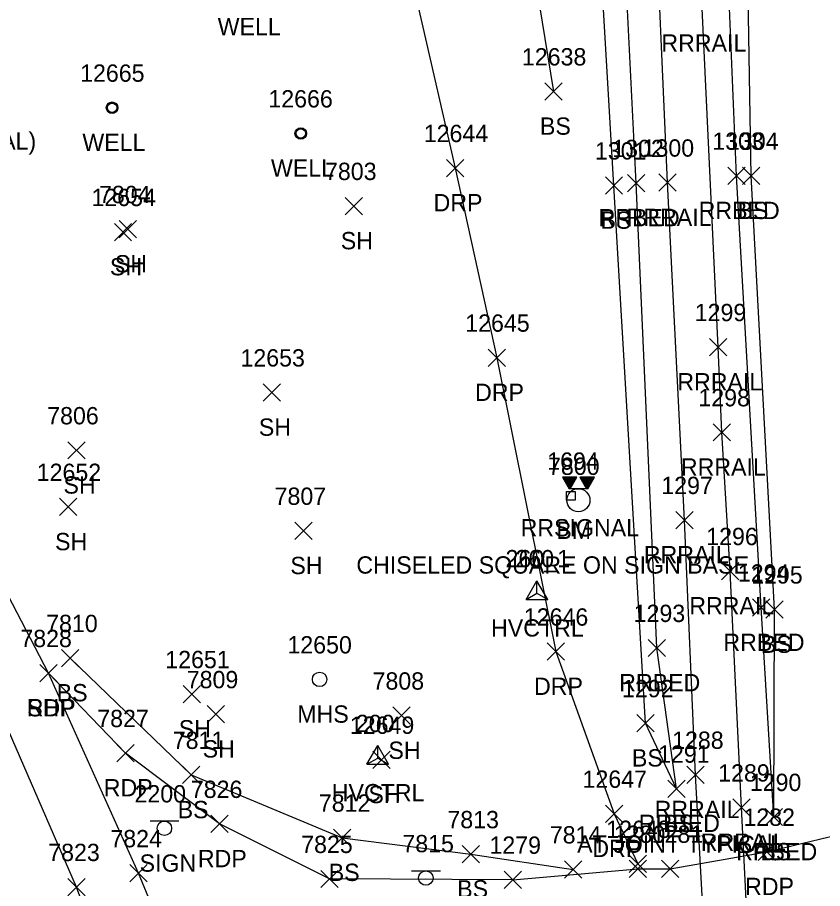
# Model space of a CAD drawing. Extents: x 1769141 to 1770817, y 735471 to 742405.
# Drawn here: x 1770083.4 to 1770176.3, y 741110.6 to 741211.2 of the extents above; entities that cross this region are included whole.
import ezdxf

# ---------------------------------------------------------------- set-up
doc = ezdxf.new("R2010")
doc.units = 0
for name, color, linetype in [('C_A', 7, 'Continuous'), ('C_C', 7, 'Continuous'), ('C_I', 7, 'Continuous'), ('CPBM', 7, 'Continuous'), ('CPSM', 7, 'Continuous'), ('L_A', 7, 'Continuous'), ('L_I', 7, 'Continuous'), ('L_TIC', 7, 'Continuous'), ('LELB', 7, 'Continuous'), ('P_A', 7, 'Continuous'), ('P_I', 7, 'Continuous'), ('P_TIC', 7, 'Continuous'), ('PET', 7, 'Continuous'), ('PSP', 7, 'Continuous'), ('R_A', 7, 'Continuous'), ('R_C', 7, 'Continuous'), ('R_I', 7, 'Continuous'), ('R_TIC', 7, 'Continuous'), ('RDP', 7, 'Continuous'), ('RR', 7, 'Continuous'), ('RRB', 7, 'Continuous'), ('S_A', 7, 'Continuous'), ('S_I', 7, 'Continuous'), ('SSGN', 7, 'Continuous'), ('TCSH', 7, 'Continuous'), ('U_A', 7, 'Continuous'), ('U_C', 7, 'Continuous'), ('U_I', 7, 'Continuous'), ('USMH', 7, 'Continuous'), ('UWW', 7, 'Continuous')]:
    doc.layers.add(name, color=color, linetype=linetype)

msp = doc.modelspace()

# ---------------------------------------------------------------- linework, layer by layer
at = {"layer": 'CPBM'}
for p, q in [((1770146.79, 741155.5), (1770146.79, 741156.5)), ((1770146.79, 741156.5), (1770147.79, 741156.5)), ((1770147.29, 741156), (1770147.29, 741156)), ((1770147.29, 741156), (1770147.29, 741156)), ((1770147.79, 741156.5), (1770147.79, 741155.5)), ((1770147.79, 741155.5), (1770146.79, 741155.5))]:
    msp.add_line(p, q, dxfattribs=at)
at = {"layer": 'CPSM'}
for p, q in [((1770142.12, 741144.01), (1770143.37, 741146.18)), ((1770142.12, 741144.01), (1770143.37, 741146.18)), ((1770144.62, 741144.01), (1770143.37, 741146.18)), ((1770143.37, 741144.74), (1770143.37, 741146.18)), ((1770144.62, 741144.01), (1770143.37, 741146.18)), ((1770143.37, 741144.74), (1770143.37, 741146.18)), ((1770142.12, 741144.01), (1770143.37, 741144.74)), ((1770142.12, 741144.01), (1770143.37, 741144.74)), ((1770143.37, 741144.74), (1770143.37, 741144.74)), ((1770143.37, 741144.74), (1770144.62, 741144.01)), ((1770143.37, 741144.74), (1770143.37, 741144.74)), ((1770143.37, 741144.74), (1770144.62, 741144.01)), ((1770142.12, 741144.01), (1770144.62, 741144.01)), ((1770142.12, 741144.01), (1770144.62, 741144.01)), ((1770123.73, 741124.98), (1770124.98, 741127.14)), ((1770126.23, 741124.98), (1770124.98, 741127.14)), ((1770124.99, 741125.7), (1770124.98, 741127.14)), ((1770123.73, 741124.98), (1770124.99, 741125.7)), ((1770124.99, 741125.7), (1770124.99, 741125.7)), ((1770124.99, 741125.7), (1770126.23, 741124.98)), ((1770123.73, 741124.98), (1770126.23, 741124.98))]:
    msp.add_line(p, q, dxfattribs=at)
at = {"layer": 'L_TIC'}
for points in [[(1770144.27, 741201.69), (1770146.27, 741203.69)], [(1770146.27, 741201.69), (1770144.27, 741203.69)], [(1770167.08, 741191.95), (1770169.08, 741193.95)], [(1770169.08, 741191.95), (1770167.08, 741193.95)], [(1770151.26, 741190.83), (1770153.26, 741192.83)], [(1770153.26, 741190.83), (1770151.26, 741192.83)], [(1770121.24, 741188.46), (1770123.24, 741190.46)], [(1770123.24, 741188.46), (1770121.24, 741190.46)], [(1770094.58, 741185.45), (1770096.58, 741187.45)], [(1770096.58, 741185.45), (1770094.58, 741187.45)], [(1770095.15, 741185.79), (1770097.15, 741187.79)], [(1770097.15, 741185.79), (1770095.15, 741187.79)], [(1770111.78, 741166.92), (1770113.78, 741168.92)], [(1770113.78, 741166.92), (1770111.78, 741168.92)], [(1770089.22, 741160.24), (1770091.22, 741162.24)], [(1770091.22, 741160.24), (1770089.22, 741162.24)], [(1770088.26, 741153.7), (1770090.26, 741155.7)], [(1770090.26, 741153.7), (1770088.26, 741155.7)], [(1770115.42, 741150.94), (1770117.42, 741152.94)], [(1770117.42, 741150.94), (1770115.42, 741152.94)], [(1770169.78, 741141.85), (1770171.78, 741143.85)], [(1770171.78, 741141.85), (1770169.78, 741143.85)], [(1770088.49, 741136.25), (1770090.49, 741138.25)], [(1770090.49, 741136.25), (1770088.49, 741138.25)], [(1770102.53, 741132.08), (1770104.53, 741134.08)], [(1770104.53, 741132.08), (1770102.53, 741134.08)], [(1770105.29, 741129.76), (1770107.29, 741131.76)], [(1770107.29, 741129.76), (1770105.29, 741131.76)], [(1770126.73, 741129.6), (1770128.73, 741131.6)], [(1770128.73, 741129.6), (1770126.73, 741131.6)], [(1770154.88, 741128.72), (1770156.88, 741130.72)], [(1770156.88, 741128.72), (1770154.88, 741130.72)], [(1770124.42, 741124.49), (1770126.42, 741126.49)], [(1770126.42, 741124.49), (1770124.42, 741126.49)], [(1770102.45, 741122.75), (1770104.45, 741124.75)], [(1770104.45, 741122.75), (1770102.45, 741124.75)], [(1770158.47, 741121.16), (1770160.47, 741123.16)], [(1770160.47, 741121.16), (1770158.47, 741123.16)], [(1770169.72, 741117.89), (1770171.72, 741119.89)], [(1770171.72, 741117.89), (1770169.72, 741119.89)], [(1770119.89, 741115.5), (1770121.89, 741117.5)], [(1770121.89, 741115.5), (1770119.89, 741117.5)], [(1770134.72, 741113.59), (1770136.72, 741115.59)], [(1770136.72, 741113.59), (1770134.72, 741115.59)], [(1770146.55, 741111.83), (1770148.55, 741113.83)], [(1770148.55, 741111.83), (1770146.55, 741113.83)]]:
    msp.add_lwpolyline(points, dxfattribs=at)
at = {"layer": 'LELB'}
for points in [[(1770159.47, 741122.16), (1770155.88, 741129.72), (1770152.26, 741191.83), (1770148.79, 741250.94), (1770147.9, 741304.26), (1770146.46, 741364.5), (1770147.88, 741419.38), (1770149.7, 741479.08), (1770152.69, 741545.1), (1770155.76, 741599.64), (1770158.96, 741639.34), (1770162.27, 741670.36), (1770169.16, 741728.31), (1770174.08, 741769.97), (1770179.32, 741804.69), (1770187.63, 741847.88), (1770194.61, 741886.57)], [(1770170.72, 741118.89), (1770170.78, 741142.85), (1770168.08, 741192.95), (1770167.14, 741250.65), (1770163.56, 741305.09), (1770162.91, 741364.69), (1770162.95, 741418.42), (1770164.45, 741477.75), (1770168.47, 741544.61), (1770171.96, 741598.42), (1770177.16, 741637.54), (1770178.36, 741670.05), (1770184.18, 741725.16), (1770189.43, 741766.84), (1770194.19, 741801.42), (1770201.5, 741845.17), (1770207.42, 741883.86)], [(1770138.33, 741423.16), (1770133.9, 741361.32), (1770128.63, 741312.35), (1770126.33, 741301.84), (1770135.84, 741298.8), (1770136.67, 741255.46), (1770145.27, 741202.69)], [(1770089.49, 741137.25), (1770103.45, 741123.75), (1770120.89, 741116.5), (1770135.72, 741114.59), (1770147.55, 741112.83)]]:
    msp.add_lwpolyline(points, dxfattribs=at)
at = {"layer": 'P_TIC'}
for points in [[(1770085.99, 741134.51), (1770087.99, 741136.51)], [(1770087.99, 741134.51), (1770085.99, 741136.51)], [(1770085.99, 741134.51), (1770087.99, 741136.51)], [(1770087.99, 741134.51), (1770085.99, 741136.51)], [(1770094.87, 741125.27), (1770096.87, 741127.27)], [(1770096.87, 741125.27), (1770094.87, 741127.27)], [(1770105.73, 741117.09), (1770107.73, 741119.09)], [(1770107.73, 741117.09), (1770105.73, 741119.09)], [(1770168.9, 741113.87), (1770170.9, 741115.87)], [(1770170.9, 741113.87), (1770168.9, 741115.87)], [(1770154.01, 741111.9), (1770156.01, 741113.9)], [(1770156.01, 741111.9), (1770154.01, 741113.9)], [(1770157.73, 741111.91), (1770159.73, 741113.91)], [(1770159.73, 741111.91), (1770157.73, 741113.91)], [(1770096.38, 741111.39), (1770098.38, 741113.39)], [(1770098.38, 741111.39), (1770096.38, 741113.39)], [(1770118.41, 741110.73), (1770120.41, 741112.73)], [(1770120.41, 741110.73), (1770118.41, 741112.73)], [(1770139.58, 741110.64), (1770141.58, 741112.64)], [(1770141.58, 741110.64), (1770139.58, 741112.64)], [(1770089.21, 741109.8), (1770091.21, 741111.8)], [(1770091.21, 741109.8), (1770089.21, 741111.8)]]:
    msp.add_lwpolyline(points, dxfattribs=at)
at = {"layer": 'PET'}
for points in [[(1770133.59, 741007.28), (1770116.34, 741046.84), (1770099.4, 741086.12), (1770090.21, 741110.8), (1770080.18, 741133.86), (1770069.42, 741160.68), (1770059.06, 741185.91)], [(1770119.41, 741111.73), (1770106.73, 741118.09), (1770095.87, 741126.27), (1770086.99, 741135.51)], [(1770140.58, 741111.64), (1770155.01, 741112.9), (1770158.73, 741112.91), (1770169.9, 741114.87), (1770181.1, 741117.58), (1770187.57, 741118.74), (1770200.24, 741121.92), (1770219.15, 741127.59)], [(1770140.58, 741111.64), (1770119.41, 741111.73)]]:
    msp.add_lwpolyline(points, dxfattribs=at)
at = {"layer": 'PSP'}
msp.add_lwpolyline([(1770137.13, 741008.17), (1770123.03, 741049.87), (1770106.81, 741089.63), (1770097.38, 741112.39), (1770086.99, 741135.51), (1770073.46, 741161.45), (1770063.93, 741186.81)], dxfattribs=at)
at = {"layer": 'R_TIC'}
for points in [[(1770132.94, 741192.84), (1770134.94, 741194.84)], [(1770134.94, 741192.84), (1770132.94, 741194.84)], [(1770153.83, 741191.11), (1770155.83, 741193.11)], [(1770155.83, 741191.11), (1770153.83, 741193.11)], [(1770157.42, 741191.16), (1770159.42, 741193.16)], [(1770159.42, 741191.16), (1770157.42, 741193.16)], [(1770165.39, 741191.95), (1770167.39, 741193.95)], [(1770167.39, 741191.95), (1770165.39, 741193.95)], [(1770163.28, 741172.16), (1770165.28, 741174.16)], [(1770165.28, 741172.16), (1770163.28, 741174.16)], [(1770137.73, 741170.94), (1770139.73, 741172.94)], [(1770139.73, 741170.94), (1770137.73, 741172.94)], [(1770163.69, 741162.32), (1770165.69, 741164.32)], [(1770165.69, 741162.32), (1770163.69, 741164.32)], [(1770159.41, 741152.19), (1770161.41, 741154.19)], [(1770161.41, 741152.19), (1770159.41, 741154.19)], [(1770164.66, 741146.29), (1770166.66, 741148.29)], [(1770166.66, 741146.29), (1770164.66, 741148.29)], [(1770168.25, 741142.07), (1770170.25, 741144.07)], [(1770170.25, 741142.07), (1770168.25, 741144.07)], [(1770144.54, 741136.99), (1770146.54, 741138.99)], [(1770146.54, 741136.99), (1770144.54, 741138.99)], [(1770156.22, 741137.41), (1770158.22, 741139.41)], [(1770158.22, 741137.41), (1770156.22, 741139.41)], [(1770160.66, 741122.76), (1770162.66, 741124.76)], [(1770162.66, 741122.76), (1770160.66, 741124.76)], [(1770158.47, 741121.16), (1770160.47, 741123.16)], [(1770160.47, 741121.16), (1770158.47, 741123.16)], [(1770165.99, 741118.98), (1770167.99, 741120.98)], [(1770167.99, 741118.98), (1770165.99, 741120.98)], [(1770151.27, 741118.26), (1770153.27, 741120.26)], [(1770153.27, 741118.26), (1770151.27, 741120.26)], [(1770169.72, 741117.89), (1770171.72, 741119.89)], [(1770171.72, 741117.89), (1770169.72, 741119.89)], [(1770154, 741112.47), (1770156, 741114.47)], [(1770156, 741112.47), (1770154, 741114.47)]]:
    msp.add_lwpolyline(points, dxfattribs=at)
at = {"layer": 'RDP'}
msp.add_lwpolyline([(1770119.07, 741298.17), (1770129.43, 741296.15), (1770123.39, 741257.98), (1770122.93, 741246.96), (1770125.26, 741231.62), (1770133.94, 741193.84), (1770138.73, 741171.94), (1770145.54, 741137.99), (1770152.27, 741119.26), (1770155, 741113.47)], dxfattribs=at)
at = {"layer": 'RR'}
for points in [[(1770197.75, 740390.49), (1770195.85, 740429.49), (1770193.92, 740468.48), (1770191.99, 740507.45), (1770190.02, 740546.42), (1770188.18, 740585.45), (1770186.34, 740624.52), (1770184.35, 740663.53), (1770182.41, 740702.58), (1770181.02, 740730.45), (1770179.25, 740766.27), (1770177.16, 740810.3), (1770173.74, 740877.11), (1770171.32, 740927.71), (1770169.45, 740967.98), (1770167.61, 741006.36), (1770166.54, 741027.4), (1770165.65, 741046.21), (1770163.84, 741084.65), (1770161.66, 741123.76), (1770160.41, 741153.19), (1770158.42, 741192.16), (1770156.87, 741228.02)], [(1770203.66, 740370.75), (1770201.77, 740409.67), (1770199.78, 740448.72), (1770197.9, 740487.78), (1770195.96, 740526.73), (1770194.09, 740565.77), (1770192.14, 740604.84), (1770190.28, 740643.85), (1770188.29, 740682.87), (1770186.41, 740721.83), (1770184.15, 740770), (1770182.62, 740801.29), (1770179.63, 740862.12), (1770176.86, 740918.91), (1770174.1, 740971.71), (1770172.22, 741013.51), (1770171.36, 741030.47), (1770170.33, 741051.22), (1770168.96, 741081.09), (1770166.99, 741119.98), (1770165.66, 741147.29), (1770164.69, 741163.32), (1770164.28, 741173.16), (1770162.44, 741212.29)]]:
    msp.add_lwpolyline(points, dxfattribs=at)
at = {"layer": 'RRB'}
for points in [[(1770159.47, 741122.16), (1770157.22, 741138.41), (1770154.83, 741192.11), (1770151.88, 741250.64), (1770151.59, 741304.35), (1770150.34, 741364.24), (1770150.63, 741419.36), (1770151.12, 741479.07), (1770155.02, 741545.1), (1770158.66, 741599.97), (1770162.08, 741639.22), (1770165.85, 741670.35), (1770171.87, 741726.99), (1770176.74, 741769), (1770181.57, 741804.32), (1770188.88, 741847.51), (1770194.61, 741886.57), (1770198.24, 741898.62)], [(1770170.72, 741118.89), (1770169.25, 741143.07), (1770166.39, 741192.95), (1770164.02, 741250.29), (1770162.37, 741304.75), (1770161.63, 741364.62), (1770161.73, 741418.13), (1770163.48, 741477.78), (1770166.12, 741544.52), (1770169.96, 741598.79), (1770173.92, 741637.73), (1770176.8, 741669.78), (1770182.94, 741725.6), (1770188.11, 741766.81), (1770193.15, 741801.76), (1770199.69, 741845.61), (1770207.42, 741883.86)]]:
    msp.add_lwpolyline(points, dxfattribs=at)
at = {"layer": 'SSGN'}
for p, q in [((1770098.71, 741118.43), (1770102.04, 741118.43)), ((1770100.36, 741117.59), (1770100.36, 741117.59)), ((1770128.9, 741112.68), (1770132.23, 741112.68)), ((1770130.54, 741111.84), (1770130.54, 741111.84))]:
    msp.add_line(p, q, dxfattribs=at)
for centre in [(1770100.36, 741117.59), (1770130.54, 741111.84)]:
    msp.add_circle(centre, 0.833, dxfattribs=at)
at = {"layer": 'TCSH'}
for p, q in [((1770147.96, 741158.14), (1770146.3, 741158.14)), ((1770146.3, 741158.14), (1770147.07, 741156.81)), ((1770147.2, 741156.81), (1770147.96, 741158.14)), ((1770150, 741158.14), (1770148.33, 741158.14)), ((1770148.33, 741158.14), (1770149.1, 741156.81)), ((1770149.23, 741156.81), (1770150, 741158.14)), ((1770149.23, 741156.81), (1770147.07, 741156.81)), ((1770148.15, 741155.48), (1770148.15, 741155.48))]:
    msp.add_line(p, q, dxfattribs=at)
for points in [[(1770146.34, 741158.07), (1770147.92, 741158.07)], [(1770146.42, 741157.93), (1770147.84, 741157.93)], [(1770146.5, 741157.8), (1770147.77, 741157.8)], [(1770148.36, 741158.1), (1770149.97, 741158.1)], [(1770148.44, 741157.96), (1770149.89, 741157.96)], [(1770148.51, 741157.83), (1770149.82, 741157.83)], [(1770146.57, 741157.67), (1770147.69, 741157.67)], [(1770146.65, 741157.53), (1770147.61, 741157.53)], [(1770146.73, 741157.4), (1770147.54, 741157.4)], [(1770146.8, 741157.27), (1770147.46, 741157.27)], [(1770146.88, 741157.13), (1770147.38, 741157.13)], [(1770146.96, 741157), (1770147.3, 741157)], [(1770147.04, 741156.87), (1770147.23, 741156.87)], [(1770148.59, 741157.7), (1770149.74, 741157.7)], [(1770148.67, 741157.56), (1770149.66, 741157.56)], [(1770148.75, 741157.43), (1770149.59, 741157.43)], [(1770148.82, 741157.3), (1770149.51, 741157.3)], [(1770148.9, 741157.16), (1770149.43, 741157.16)], [(1770148.98, 741157.03), (1770149.36, 741157.03)], [(1770149.05, 741156.9), (1770149.28, 741156.9)]]:
    msp.add_lwpolyline(points, dxfattribs=at)
msp.add_circle((1770148.15, 741155.48), 1.33, dxfattribs=at)
at = {"layer": 'USMH'}
for p, q in [((1770118.28, 741134.78), (1770118.28, 741134.78)), ((1770119.12, 741134.78), (1770119.12, 741134.78))]:
    msp.add_line(p, q, dxfattribs=at)
msp.add_circle((1770118.28, 741134.78), 0.833, dxfattribs=at)
at = {"layer": 'UWW'}
for centre, radius in [((1770094.32, 741200.81), 0.667), ((1770094.32, 741200.81), 0.625), ((1770094.32, 741200.81), 0.583), ((1770094.32, 741200.81), 0.542), ((1770116.1, 741197.84), 0.667), ((1770116.1, 741197.84), 0.625), ((1770116.1, 741197.84), 0.583), ((1770116.1, 741197.84), 0.542)]:
    msp.add_circle(centre, radius, dxfattribs=at)

# ---------------------------------------------------------------- texts
at = {"layer": 'C_A'}
for s, p in [('BM', (1770145.6, 741151)), ('HVCTRL', (1770138.07, 741139.73)), ('HVCTRL', (1770138.07, 741139.73)), ('HVCTRL', (1770119.68, 741120.7))]:
    msp.add_text(s, height=2, dxfattribs=at).set_placement(p)
at = {"layer": 'C_C'}
msp.add_text('CHISELED SQUARE ON SIGN BASE', height=2, dxfattribs=at).set_placement((1770122.52, 741147))
at = {"layer": 'C_I'}
for s, p in [('1694', (1770144.55, 741159)), ('260_1', (1770139.74, 741147.73)), ('260', (1770140.88, 741147.73)), ('200', (1770122.46, 741128.7))]:
    msp.add_text(s, height=2, dxfattribs=at).set_placement(p)
at = {"layer": 'L_A'}
for s, p in [('BS', (1770143.71, 741197.69)), ('BS', (1770166.52, 741187.95)), ('BS', (1770150.7, 741186.83)), ('SH', (1770120.72, 741184.46)), ('SH', (1770094.07, 741181.45)), ('SH', (1770094.64, 741181.79)), ('SH', (1770111.26, 741162.92)), ('SH', (1770088.71, 741156.24)), ('SH', (1770087.74, 741149.7)), ('SH', (1770114.9, 741146.94)), ('BS', (1770169.22, 741137.85)), ('BS', (1770087.93, 741132.25)), ('SH', (1770102.02, 741128.08)), ('SH', (1770104.78, 741125.76)), ('SH', (1770126.22, 741125.6)), ('BS', (1770154.33, 741124.72)), ('SH', (1770123.91, 741120.49)), ('BS', (1770101.89, 741118.75)), ('BS', (1770157.92, 741117.16)), ('BS', (1770169.16, 741113.89)), ('BS', (1770119.33, 741111.5)), ('BS', (1770134.16, 741109.59))]:
    msp.add_text(s, height=2, dxfattribs=at).set_placement(p)
at = {"layer": 'L_I'}
for s, p in [('12638', (1770141.63, 741205.69)), ('1304', (1770165.31, 741195.95)), ('1301', (1770150.06, 741194.83)), ('7803', (1770118.9, 741192.46)), ('12654', (1770091.94, 741189.45)), ('7804', (1770092.81, 741189.79)), ('12653', (1770109.14, 741170.92)), ('7806', (1770086.83, 741164.24)), ('12652', (1770085.62, 741157.7)), ('7807', (1770113.08, 741154.94)), ('1295', (1770168.09, 741145.85)), ('7810', (1770086.71, 741140.25)), ('12651', (1770100.46, 741136.08)), ('7809', (1770102.94, 741133.76)), ('7808', (1770124.39, 741133.6)), ('1292', (1770153.19, 741132.72)), ('12649', (1770121.77, 741128.49)), ('7811', (1770101.33, 741126.75)), ('1291', (1770157.35, 741125.16)), ('1290', (1770167.94, 741121.89)), ('7812', (1770118.19, 741119.5)), ('7813', (1770133.03, 741117.59)), ('7814', (1770144.85, 741115.83))]:
    msp.add_text(s, height=2, dxfattribs=at).set_placement(p)
at = {"layer": 'P_A'}
for s, p in [('SHP', (1770084.52, 741130.51)), ('RDP', (1770084.47, 741130.51)), ('RDP', (1770093.36, 741121.27)), ('RDP', (1770104.22, 741113.09)), ('RDP', (1770167.39, 741109.87))]:
    msp.add_text(s, height=2, dxfattribs=at).set_placement(p)
at = {"layer": 'P_I'}
for s, p in [('7828', (1770083.73, 741138.51)), ('7828', (1770083.73, 741138.51)), ('7827', (1770092.61, 741129.27)), ('7826', (1770103.41, 741121.09)), ('1282', (1770167.2, 741117.87)), ('1280', (1770152.23, 741115.9)), ('1281', (1770156.61, 741115.91)), ('7824', (1770094.12, 741115.39)), ('7825', (1770116.15, 741114.73)), ('1279', (1770137.88, 741114.64)), ('7823', (1770086.95, 741113.8))]:
    msp.add_text(s, height=2, dxfattribs=at).set_placement(p)
at = {"layer": 'R_A'}
for s, p in [('RRRAIL', (1770157.73, 741207.29)), ('DRP', (1770131.43, 741188.84)), ('RRBED', (1770150.48, 741187.11)), ('RRRAIL', (1770153.71, 741187.16)), ('RRBED', (1770162.03, 741187.95)), ('RRRAIL', (1770159.57, 741168.16)), ('DRP', (1770136.22, 741166.94)), ('RRRAIL', (1770159.98, 741158.32)), ('RRSIGNAL', (1770141.48, 741151.3)), ('RRRAIL', (1770155.7, 741148.19)), ('RRRAIL', (1770160.95, 741142.29)), ('RRBED', (1770164.89, 741138.07)), ('DRP', (1770143.03, 741132.99)), ('RRBED', (1770152.86, 741133.41)), ('RRRAIL', (1770156.95, 741118.76)), ('RRBED', (1770155.12, 741117.16)), ('RRRAIL', (1770162.28, 741114.98)), ('DRP', (1770149.76, 741114.26)), ('RRBED', (1770166.36, 741113.89))]:
    msp.add_text(s, height=2, dxfattribs=at).set_placement(p)
at = {"layer": 'R_C'}
msp.add_text('AT JOINT TYPICAL', height=2, dxfattribs=at).set_placement((1770148.01, 741114.76))
at = {"layer": 'R_I'}
for s, p in [('12644', (1770130.3, 741196.84)), ('1302', (1770152.06, 741195.11)), ('1300', (1770155.56, 741195.16)), ('1303', (1770163.61, 741195.95)), ('1299', (1770161.58, 741176.16)), ('12645', (1770135.09, 741174.94)), ('1298', (1770162, 741166.32)), ('7800', (1770144.65, 741158.4)), ('1297', (1770157.72, 741156.19)), ('1296', (1770162.91, 741150.29)), ('1294', (1770166.56, 741146.07)), ('12646', (1770141.85, 741140.99)), ('1293', (1770154.53, 741141.41)), ('1288', (1770158.97, 741126.76)), ('1291', (1770157.35, 741125.16)), ('1289', (1770164.29, 741122.98)), ('12647', (1770148.63, 741122.26)), ('1290', (1770167.94, 741121.89)), ('12648', (1770151.36, 741116.47))]:
    msp.add_text(s, height=2, dxfattribs=at).set_placement(p)
at = {"layer": 'S_A'}
msp.add_text('SIGN', height=2, dxfattribs=at).set_placement((1770097.5, 741112.57))
at = {"layer": 'S_I'}
for s, p in [('2200', (1770096.91, 741120.57)), ('7815', (1770127.83, 741114.82))]:
    msp.add_text(s, height=2, dxfattribs=at).set_placement(p)
at = {"layer": 'U_A'}
for s, p in [('WELL', (1770106.51, 741209.19)), ('WELL', (1770090.89, 741195.81)), ('WELL', (1770112.66, 741192.84)), ('MHS', (1770115.7, 741129.78))]:
    msp.add_text(s, height=2, dxfattribs=at).set_placement(p)
at = {"layer": 'U_C'}
msp.add_text('MONITOR (TYPICAL)', height=2, dxfattribs=at).set_placement((1770059.26, 741195.98))
at = {"layer": 'U_I'}
for s, p in [('12665', (1770090.63, 741203.81)), ('12666', (1770112.36, 741200.84)), ('12650', (1770114.56, 741137.78))]:
    msp.add_text(s, height=2, dxfattribs=at).set_placement(p)

doc.saveas('drawing.dxf')
